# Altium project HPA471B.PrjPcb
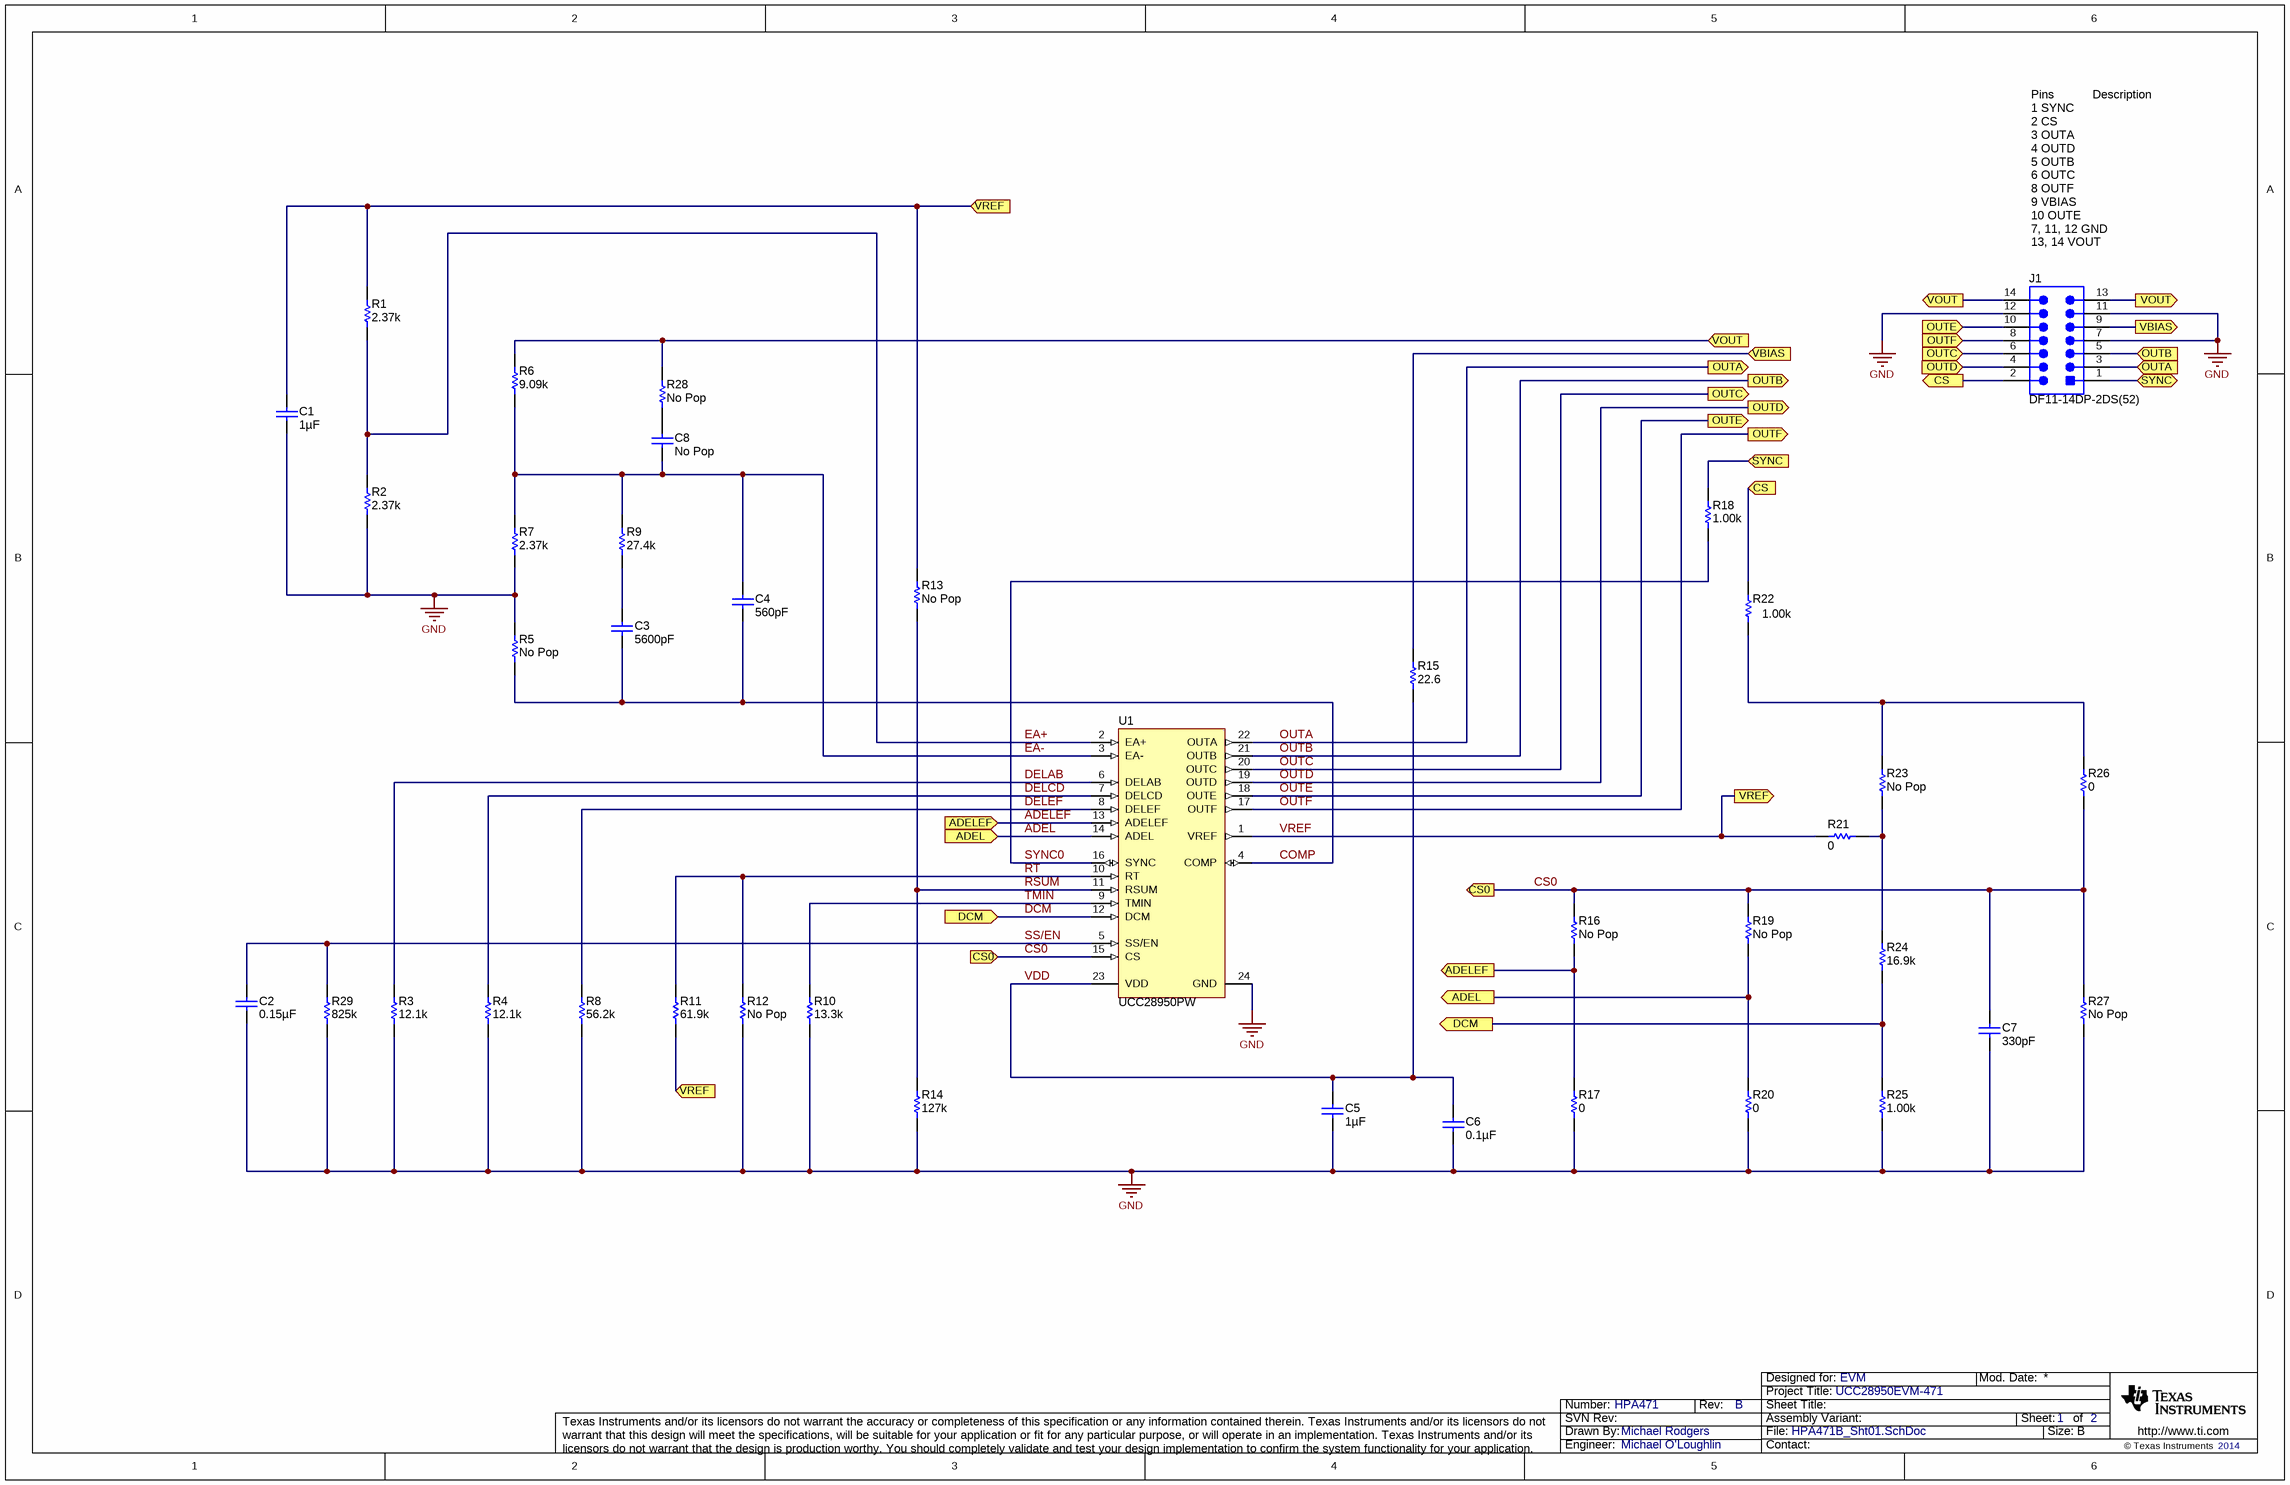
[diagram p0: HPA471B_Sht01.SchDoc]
DrawnBy: Michael Rodgers; SCH_Rev: B; PRJ_Title: UCC28950EVM-471; PRJ_Number: HPA471; PRJ_Customer: EVM; PCB_Rev: B; PCB_Layout: Michael Rodgers; CopyrightYear: 2014; PRJ_Engineer: Michael O'Loughlin
2 sheets, 48 parts. Net scope: global (net labels, ports and power ports of the same name join across sheets).
Board file: HPA471B.PcbDoc
Sheets:
  HPA471B_Sht01.SchDoc
  HPA471B_Hardware.SchDoc

## Sheet HPA471B_Sht01.SchDoc
size 431 x 279 mm; CompanyName: Texas Instruments; DocumentNumber: 1; SheetNumber: 1; SheetTotal: 2

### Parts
C1  ValueDisplayed: 1µF  [0805_HV]  (hidden comment: 08055C105KAT2A)
C2  ValueDisplayed: 0.15µF  [0805_HV]  (hidden comment: C0805C154K5RACTU)
C3  ValueDisplayed: 5600pF  [0805_HV]  (hidden comment: 08055C562KAT2A)
C4  ValueDisplayed: 560pF  [0805_HV]  (hidden comment: 08055C561KAT2A)
C5  ValueDisplayed: 1µF  [0805_HV]  (hidden comment: 08055C105KAT2A)
C6  ValueDisplayed: 0.1µF  [0805_HV]  (hidden comment: 08053C104KAT2A)
C7  ValueDisplayed: 330pF  [0805_HV]  (hidden comment: 08055C331KAT2A)
C8  ValueDisplayed: No Pop  [0805_HV]  (hidden comment: 08055C331KAT2A)
J1  DF11-14DP-2DS(52)  [Hirose_DF11-14DP-2DS_52]
R1  value 2.37k  [0805_HV]  (hidden comment: CRCW08052K37FKEA)
R2  value 2.37k  [0805_HV]  (hidden comment: CRCW08052K37FKEA)
R3  value 12.1k  [0805_HV]  (hidden comment: CRCW080512K1FKEA)
R4  value 12.1k  [0805_HV]  (hidden comment: CRCW080512K1FKEA)
R5  value No Pop  [0805_HV]  (hidden comment: CRCW08051K00FKEA)
R6  value 9.09k  [0805_HV]  (hidden comment: CRCW08059K09FKEA)
R7  value 2.37k  [0805_HV]  (hidden comment: CRCW08052K37FKEA)
R8  value 56.2k  [0805_HV]  (hidden comment: CRCW080556K2FKEA)
R9  value 27.4k  [0805_HV]  (hidden comment: CRCW080527K4FKEA)
R10  ValueDisplayed: 13.3k  [0805_HV]  (hidden comment: CRCW080513K3FKEA)
R11  value 61.9k  [0805_HV]  (hidden comment: CRCW080561K9FKEA)
R12  value No Pop  [0805_HV]  (hidden comment: CRCW08051K00FKEA)
R13  value No Pop  [0805_HV]  (hidden comment: CRCW08051K00FKEA)
R14  value 127k  [0805_HV]  (hidden comment: CRCW0805127KFKEA)
R15  value 22.6  [0805_HV]  (hidden comment: CRCW080522R6FKEA)
R16  value No Pop  [0805_HV]  (hidden comment: CRCW08051K00FKEA)
R17  value 0  [0805_HV]  (hidden comment: CRCW08050000Z0EA)
R18  value 1.00k  [0805_HV]  (hidden comment: CRCW08051K00FKEA)
R19  value No Pop  [0805_HV]  (hidden comment: CRCW08051K00FKEA)
R20  value 0  [0805_HV]  (hidden comment: CRCW08050000Z0EA)
R21  value 0  [0805_HV]  (hidden comment: CRCW08050000Z0EA)
R22  value 1.00k  [0805_HV]  (hidden comment: CRCW08051K00FKEA)
R23  value No Pop  [0805_HV]  (hidden comment: CRCW08051K00FKEA)
R24  value 16.9k  [0805_HV]  (hidden comment: CRCW080516K9FKEA)
R25  value 1.00k  [0805_HV]  (hidden comment: CRCW08051K00FKEA)
R26  value 0  [0805_HV]  (hidden comment: CRCW08050000Z0EA)
R27  value No Pop  [0805_HV]  (hidden comment: CRCW08051K00FKEA)
R28  value No Pop  [0805_HV]  (hidden comment: CRCW08051K00FKEA)
R29  value 825k  [0805_HV]  (hidden comment: CRCW0805825KFKEA)
U1  UCC28950PW  [PW0024A_N]

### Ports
ADEL (in), ADEL (out), ADELEF (in), ADELEF (out), CS0 (in), CS0 (out), CS (in), CS (out), DCM (in), DCM (out), OUTA (in), OUTA (out), OUTB (in), OUTB (out), OUTC (in), OUTC (out), OUTD (in), OUTD (out), OUTE (in), OUTE (out), OUTF (in), OUTF (out), SYNC (bidir), SYNC (in), VBIAS (in), VBIAS (out), VOUT (in), VOUT (out), VREF (in), VREF (out)

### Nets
GND: C1.1 C2.1 C5.1 C6.1 C7.1 J1.7 J1.11 J1.12 R2.1 R3.1 R4.1 R5.2 R7.1 R8.1 R10.1 R12.1 R14.1 R17.1 R20.1 R25.1 R27.1 R29.1 U1.24(GND)
ADEL: R19.1 R20.2 U1.14(ADEL) ; port ADEL
ADELEF: R16.1 R17.2 U1.13(ADELEF) ; port ADELEF
COMP: C3.1 C4.1 R5.1 U1.4(COMP)
CS: J1.2 R22.2 ; port CS
CS0: C7.2 R16.2 R19.2 R26.1 R27.2 U1.15(CS) ; port CS0
DCM: R24.1 R25.2 U1.12(DCM) ; port DCM
DELAB: R3.2 U1.6(DELAB)
DELCD: R4.2 U1.7(DELCD)
DELEF: R8.2 U1.8(DELEF)
EA+: R1.1 R2.2 U1.2(EA+)
EA-: C4.2 C8.1 R6.1 R7.2 R9.2 U1.3(EA-)
OUTA: J1.3 U1.22(OUTA) ; port OUTA
OUTB: J1.5 U1.21(OUTB) ; port OUTB
OUTC: J1.6 U1.20(OUTC) ; port OUTC
OUTD: J1.4 U1.19(OUTD) ; port OUTD
OUTE: J1.10 U1.18(OUTE) ; port OUTE
OUTF: J1.8 U1.17(OUTF) ; port OUTF
RSUM: R13.1 R14.2 U1.11(RSUM)
RT: R11.2 R12.2 U1.10(RT)
SS/EN: C2.2 R29.2 U1.5(SS/EN)
SYNC: J1.1 R18.2 ; port SYNC
SYNC0: R18.1 U1.16(SYNC)
TMIN: R10.2 U1.9(TMIN)
VBIAS: J1.9 R15.2 ; port VBIAS
VDD: C5.2 C6.2 R15.1 U1.23(VDD)
VOUT: J1.13 J1.14 R6.2 R28.2 ; port VOUT
VREF: C1.2 R1.2 R11.1 R13.2 R21.2 U1.1(VREF) ; port VREF
NetC3_2: C3.2 R9.1
NetC8_2: C8.2 R28.1
NetR21_1: R21.1 R23.1 R24.2
NetR22_1: R22.1 R23.2 R26.2

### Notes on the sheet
- Pins           Description
  1	SYNC
  2	CS
  3	OUTA
  4	OUTD
  5	OUTB
  6	OUTC
  8	OUTF
  9	VBIAS
  10	OUTE
  7, 11, 12	GND
  13, 14	VOUT

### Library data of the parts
C1 C5 = 08055C105KAT2A: CAP, CERM, 1 µF, 50 V, +/- 10%, X7R, 0805; Manufacturer: AVX; Value: 1uF; Polarized: N; CompType: Capacitor; U/M: EA; Cap_F: 0.000001; Tolerance_%: 10; Value1: Unknown; VDC_V: 50; Value2: 50V; TaMin_C: -55; TaMax_C: 125; Cap_Case: 0805
C2 = C0805C154K5RACTU: CAP, CERM, 0.15 µF, 50 V, +/- 10%, X7R, 0805; Manufacturer: Kemet; Value: 0.15uF; Polarized: N; CompType: Capacitor; U/M: EA; Cap_F: 0.00000015; Tolerance_%: 10; ESR_ohm: 0.054; Value1: 0.054 ohm; VDC_V: 50; Value2: 50V; IRMS_A: 2.09; TaMin_C: -55; TaMax_C: 125; Cap_Case: 0805
C3 = 08055C562KAT2A: CAP, CERM, 5600 pF, 50 V, +/- 10%, X7R, 0805; Manufacturer: AVX; Value: 5600pF; Polarized: N; CompType: Capacitor; U/M: EA; Cap_F: 0.0000000056; Tolerance_%: 10; ESR_ohm: 0.107; Value1: 0.107 ohm; VDC_V: 50; Value2: 50V; TaMin_C: -55; TaMax_C: 125; Cap_Case: 0805
C4 = 08055C561KAT2A: CAP, CERM, 560 pF, 50 V, +/- 10%, X7R, 0805; Manufacturer: AVX; Value: 560pF; Polarized: N; CompType: Capacitor; U/M: EA; Cap_F: 0.00000000056; Tolerance_%: 10; ESR_ohm: 0.409; Value1: 0.409 ohm; VDC_V: 50; Value2: 50V; TaMin_C: -55; TaMax_C: 125; Cap_Case: 0805
C6 = 08053C104KAT2A: CAP, CERM, 0.1 µF, 25 V, +/- 10%, X7R, 0805; Manufacturer: AVX; Value: 0.1uF; Polarized: N; CompType: Capacitor; U/M: EA; Cap_F: 0.0000001; Tolerance_%: 10; ESR_ohm: 0.28; Value1: 0.28 ohm; VDC_V: 25; Value2: 25V; TaMin_C: -55; TaMax_C: 125; Cap_Case: 0805
C7 C8 = 08055C331KAT2A: CAP, CERM, 330 pF, 50 V, +/- 10%, X7R, 0805; Manufacturer: AVX; Value: 330pF; Polarized: N; CompType: Capacitor; U/M: EA; Cap_F: 0.00000000033; Tolerance_%: 10; ESR_ohm: 0.563; Value1: 0.563 ohm; VDC_V: 50; Value2: 50V; TaMin_C: -55; TaMax_C: 125; Cap_Case: 0805
J1 = DF11-14DP-2DS(52): Header (shrouded), 2 mm, 7x2, R/A, TH; Manufacturer: Hirose Electric Co. Ltd.; SymbolCreator: a0412235; U/M: EA
R1 R2 R7 = CRCW08052K37FKEA: RES, 2.37k ohm, 1%, 0.125W, 0805; Manufacturer: Vishay-Dale; CompType: Resistor; Res_ohm: 2370; Value_Code: 2k37; Tolerance_%: 1; Power_W: 0.125; VDC_V: 150; TempCo: 100 ppm/C; EIA_Code: E96; U/M: EA
R3 R4 = CRCW080512K1FKEA: RES, 12.1k ohm, 1%, 0.125W, 0805; Manufacturer: Vishay-Dale; CompType: Resistor; Res_ohm: 12100; Value_Code: 12k1; Tolerance_%: 1; Power_W: 0.125; VDC_V: 150; TempCo: 100 ppm/C; EIA_Code: E96; U/M: EA
R5 R12 R13 R16 R18 R19 R22 R23 R25 R27 R28 = CRCW08051K00FKEA: RES, 1.00k ohm, 1%, 0.125W, 0805; Manufacturer: Vishay-Dale; CompType: Resistor; Res_ohm: 1000; Value_Code: 1k00; Tolerance_%: 1; Power_W: 0.125; VDC_V: 150; TempCo: 100 ppm/C; EIA_Code: E96; U/M: EA
R6 = CRCW08059K09FKEA: RES, 9.09k ohm, 1%, 0.125W, 0805; Manufacturer: Vishay-Dale; CompType: Resistor; Res_ohm: 9090; Value_Code: 9k09; Tolerance_%: 1; Power_W: 0.125; VDC_V: 150; TempCo: 100 ppm/C; EIA_Code: E96; U/M: EA
R8 = CRCW080556K2FKEA: RES, 56.2k ohm, 1%, 0.125W, 0805; Manufacturer: Vishay-Dale; CompType: Resistor; Res_ohm: 56200; Value_Code: 56k2; Tolerance_%: 1; Power_W: 0.125; VDC_V: 150; TempCo: 100 ppm/C; EIA_Code: E96; U/M: EA
R9 = CRCW080527K4FKEA: RES, 27.4k ohm, 1%, 0.125W, 0805; Manufacturer: Vishay-Dale; CompType: Resistor; Res_ohm: 27400; Value_Code: 27k4; Tolerance_%: 1; Power_W: 0.125; VDC_V: 150; TempCo: 100 ppm/C; EIA_Code: E96; U/M: EA
R10 = CRCW080513K3FKEA: RES, 13.3 k, 1%, 0.125 W, 0805; Manufacturer: Vishay-Dale; Value: 13.3k; CompType: Resistor; Res_ohm: 13300; Value_Code: 13k3; Tolerance_%: 1; Power_W: 0.125; Value2: 0.125W; VDC_V: 150; TempCo: 100 ppm/C; EIA_Code: E96; U/M: EA
R11 = CRCW080561K9FKEA: RES, 61.9k ohm, 1%, 0.125W, 0805; Manufacturer: Vishay-Dale; CompType: Resistor; Res_ohm: 61900; Value_Code: 61k9; Tolerance_%: 1; Power_W: 0.125; VDC_V: 150; TempCo: 100 ppm/C; EIA_Code: E96; U/M: EA
R14 = CRCW0805127KFKEA: RES, 127k ohm, 1%, 0.125W, 0805; Manufacturer: Vishay-Dale; CompType: Resistor; Res_ohm: 127000; Tolerance_%: 1; Power_W: 0.125; VDC_V: 150; TempCo: 100 ppm/C; EIA_Code: E96; U/M: EA
R15 = CRCW080522R6FKEA: RES, 22.6 ohm, 1%, 0.125W, 0805; Manufacturer: Vishay-Dale; CompType: Resistor; Value_Code: 22R6; Tolerance_%: 1; Power_W: 0.125; VDC_V: 150; TempCo: 100 ppm/C; EIA_Code: E96; U/M: EA
R17 R20 R21 R26 = CRCW08050000Z0EA: RES, 0 ohm, 5%, 0.125W, 0805; Manufacturer: Vishay-Dale; CompType: Resistor; Value_Code: 0000; Tolerance_%: 5; Power_W: 0.125; VDC_V: 150; TempCo: 200 ppm/C; EIA_Code: E24; U/M: EA
R24 = CRCW080516K9FKEA: RES, 16.9k ohm, 1%, 0.125W, 0805; Manufacturer: Vishay-Dale; CompType: Resistor; Res_ohm: 16900; Value_Code: 16k9; Tolerance_%: 1; Power_W: 0.125; VDC_V: 150; TempCo: 100 ppm/C; EIA_Code: E96; U/M: EA
R29 = CRCW0805825KFKEA: RES, 825k ohm, 1%, 0.125W, 0805; Manufacturer: Vishay-Dale; CompType: Resistor; Res_ohm: 825000; Tolerance_%: 1; Power_W: 0.125; VDC_V: 150; TempCo: 100 ppm/C; EIA_Code: E96; U/M: EA
U1 = UCC28950PW: Green Phase-Shifted Full-Bridge Controller with Synchronous Rectification with Current Control, 97 % Duty Cycle, -40 to +125 degC, 24-pin TSSOP (PW), Green (RoHS & no Sb/Br); Manufacturer: Texas Instruments; Alternate Manufacturer: None; Alternate PartNumber: Equivalent; Duty Cycle(Max)(%): 97; Frequency(Max)(kHz): 1000; Rating: Catalog; Regulated Outputs(#): 1; SubFamily: PWM Controller; UVLO Thresholds On/Off(V): 6.75min/6.15min

## Sheet HPA471B_Hardware.SchDoc
size 431 x 279 mm; Date: Not shown in title block; ApprovedBy: Not shown in title block; CheckedBy: Not shown in title block; Author: Not shown in title block; CompanyName: Texas Instruments; Engineer: Not shown in title block; Organization: Not shown in title block; Address1: Not shown in title block; Address2: Not shown in title block; Address3: Not shown in title block; Address4: Not shown in title block; DocumentNumber: 2; Revision: Use project parameter SCH_Rev; SheetNumber: 2; SheetTotal: 2; PageSetup: Record=PageOptions|CenterHorizontal=True|CenterVertical=True|PrintScale=1.00|XCorrection=1.00|YCorrection=1.00|PrintKind=0|BorderSize=5000000|LeftOffset=0|BottomOffset=0|Orientation=2|PaperLength=1000|PaperWidth=1000|Scale=100|PaperSource=15|PrintQuality=600|MediaType=1|DitherType=10|PaperKind=Letter|PrintScaleMode=1
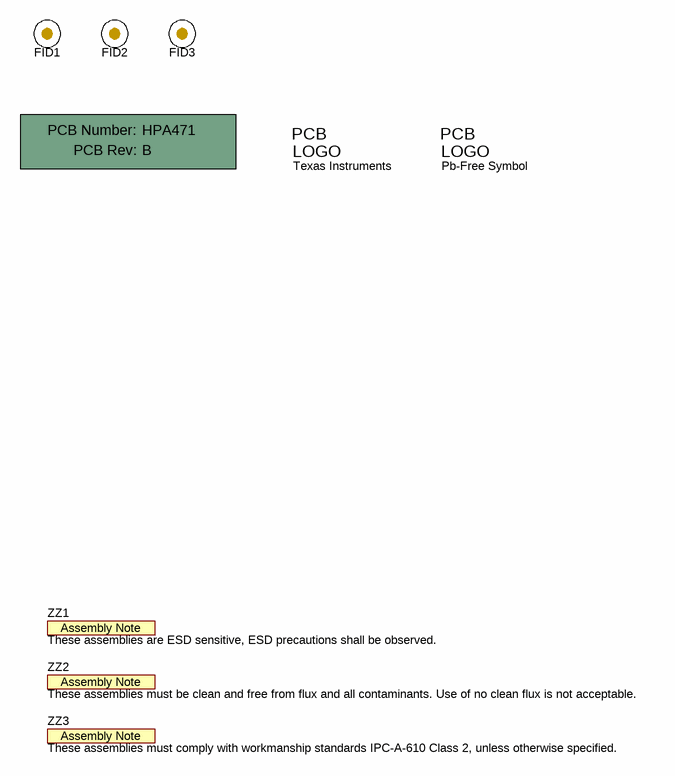
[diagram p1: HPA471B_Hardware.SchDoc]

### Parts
!PCB  Printed Circuit Board  (value not drawn)  (mechanical)
FID1  Fiducial  [Fiducial6.4-20]  (value not drawn)
FID2  Fiducial  [Fiducial6.4-20]  (value not drawn)
FID3  Fiducial  [Fiducial6.4-20]  (value not drawn)
Logo1  Texas Instruments  [TI_Stacked_Overlay_Small]  (no BOM)
Logo2  Pb-Free Symbol  [Pb-Free_Overlay_Small]  (no BOM)
ZZ1  These assemblies are ESD sensitive, ESD precautions shall be observed.  [AssemblyNote]  (no BOM)
ZZ2  These assemblies must be clean and free from flux and all contaminants. Use of no clean flux is not acceptable.  [AssemblyNote]  (no BOM)
ZZ3  These assemblies must comply with workmanship standards IPC-A-610 Class 2, unless otherwise specified.  [AssemblyNote]  (no BOM)

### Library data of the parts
!PCB = PCB: Manufacturer: Any; PartNumber: HPA471; SymbolCreator: a0412235
FID1-FID3 = Fiducial: Fiducial mark.  There is nothing to buy or mount.; SymbolCreator: codlsc
Logo1 = TI_Logo: Texas Instrument Corporate Signature; SymbolCreator: a0412235
Logo2 = Pb-Free: SymbolCreator: a0412235
ZZ1-ZZ3 = AssemblyNote: SymbolCreator: codlsc

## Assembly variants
001: not fitted C8 FID1 FID2 FID3 R5 R12 R13 R16 R19 R23 R27 R28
